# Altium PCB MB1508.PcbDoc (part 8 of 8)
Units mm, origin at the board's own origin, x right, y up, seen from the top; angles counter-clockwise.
Board outline 129 x 77 mm, 4 copper layers (Top Layer, GND, POWER, Bottom Layer), stack 1.582 mm thick; 399 components, 297 nets, 1407 pads, 1316 vias.
Unrouted connection lines stored in the file: 535.
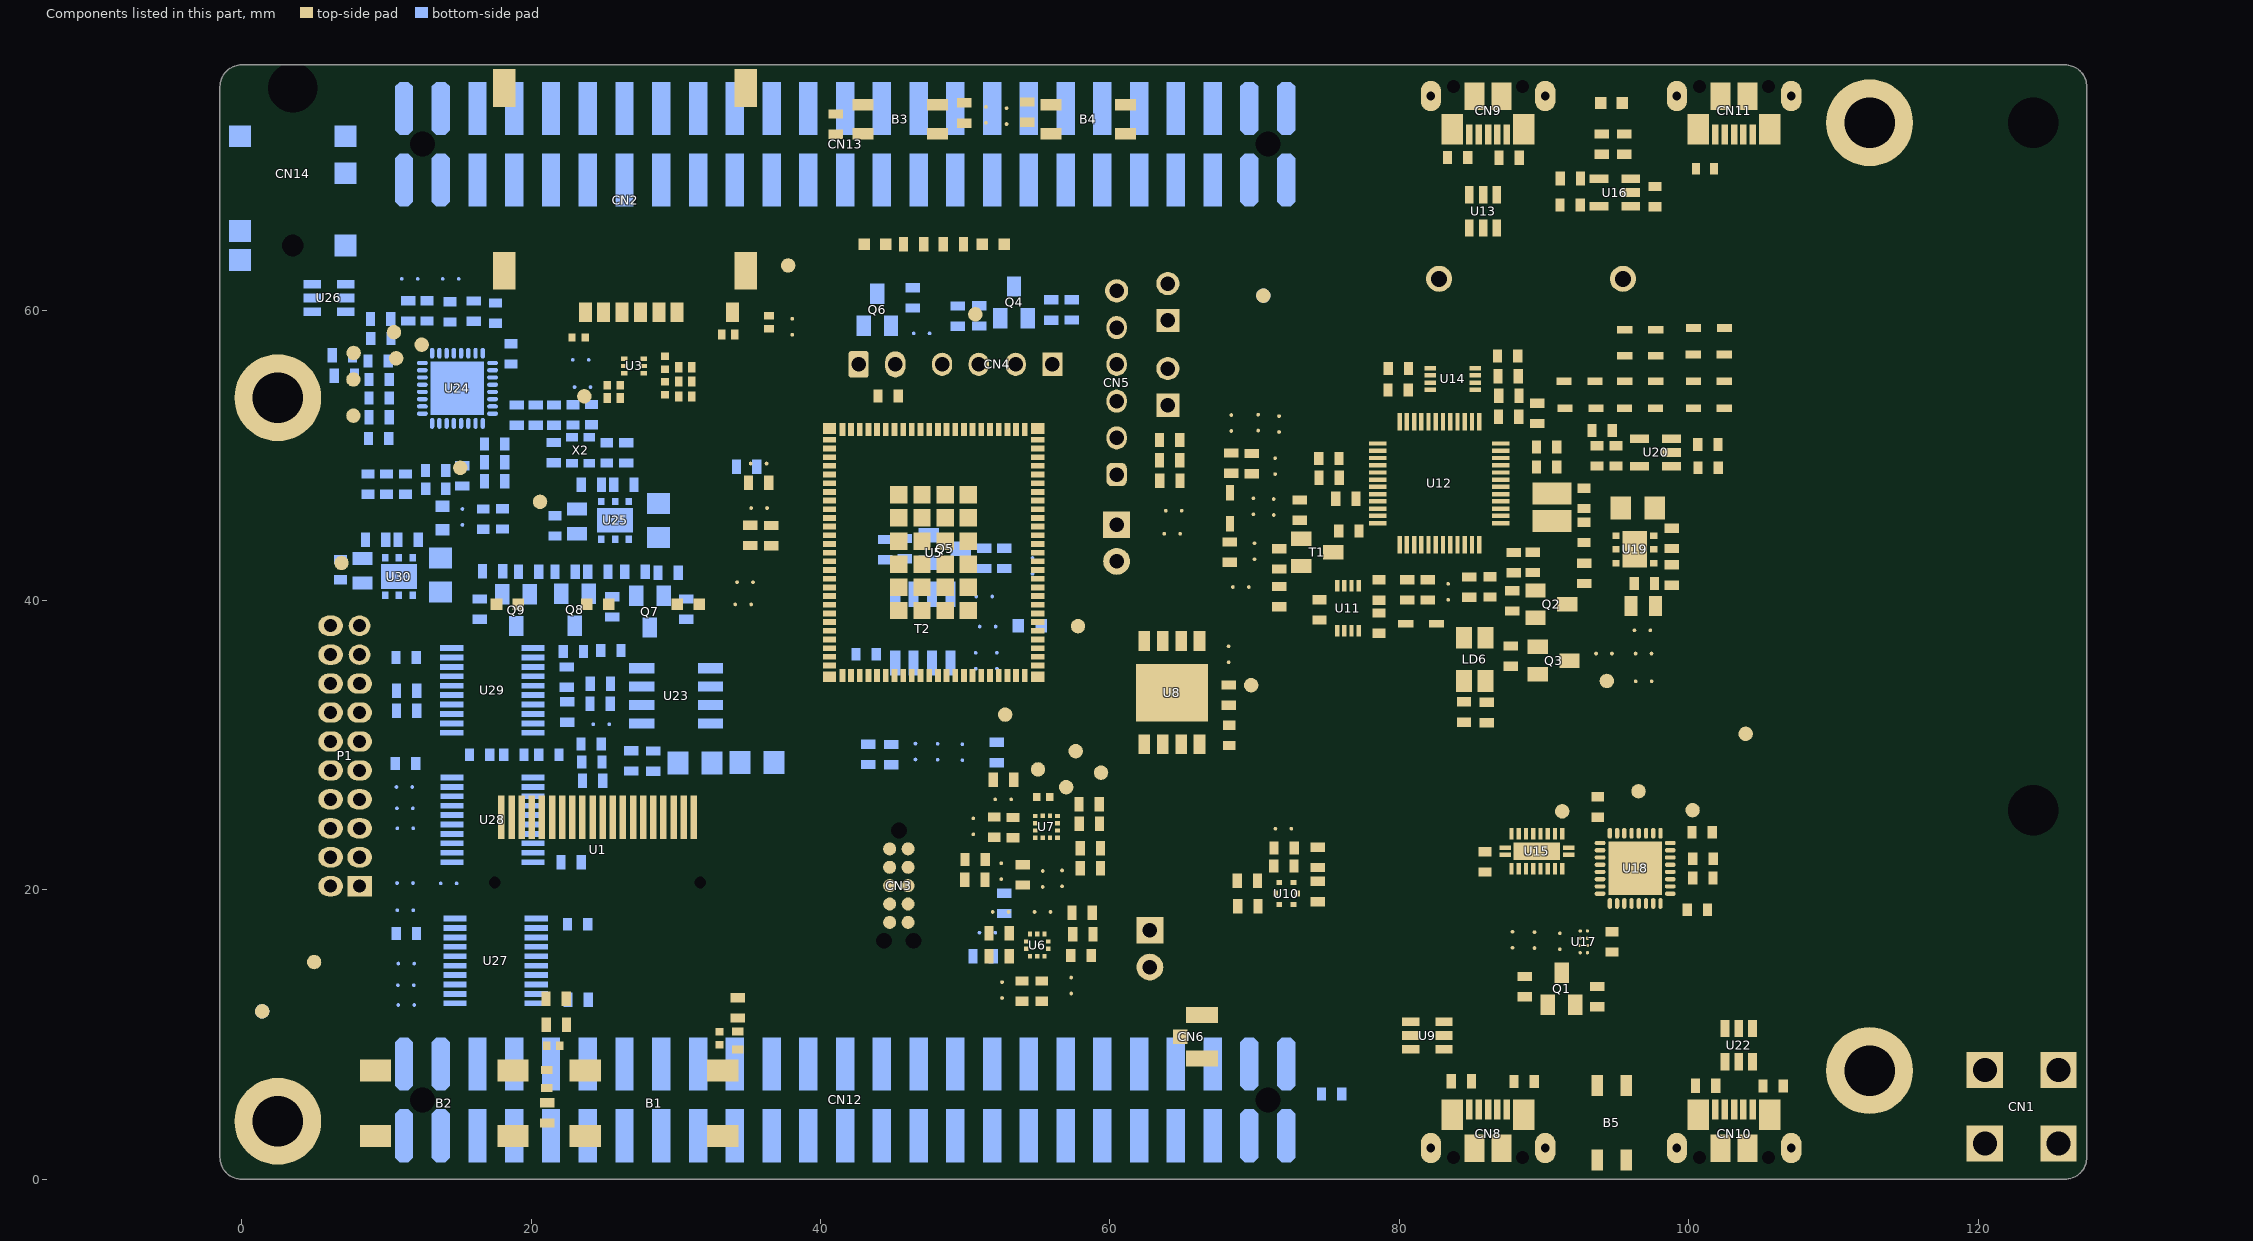
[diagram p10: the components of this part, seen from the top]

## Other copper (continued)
Bottom Layer:
  rectangle net 3V3: 21.08,45.83 23.352,46.772
  rectangle net 3V3: 24.95,37.795 26.145,38.78
  rectangle net 1V8: 25.866,35.418 27.034,36.242
  rectangle net GND: 27.675,43.641 30.07,45.734
  rectangle net GND: 23.59,16.793 24.556,18.111
  rectangle net GND: 22.77,20.927 24.204,22.403
  rectangle net GND: 45.498,43.506 48.489,44.882
  rectangle net GND: 52.228,41.367 53.296,42.509
  rectangle net GND: 52.075,58.551 53.483,60.041
  rectangle net GND: 54.985,60.516 56.469,61.426
  rectangle net GND: 27.96,29.02 29.112,29.923
  rectangle net GND: 31.313,27.459 32.618,29.897
  rectangle net GND: 42.5,58.337 43.844,59.956
  rectangle net GND: 9.94,27.943 11.291,29.567
  rectangle net GND: 10.099,35.382 11.375,36.741
  rectangle net GND: 28.26,39.289 29.402,40.88
  region net GND: 41.285,10.315 40.618,10.143 40.435,9.96 40.532,9.864 40.532,9.745 40.636,9.868 41.211,10.095
  region net GND: 41.211,10.095
  pour cut-out: 11.823,67.466 13.444,67.466 13.486,67.509 13.486,71.973 13.022,72.437 11.406,72.437 11.406,72.33 11.207,72.131
  pour cut-out: 10.31,71.79 10.273,71.752 10.273,70.568 10.683,70.568 11.036,70.92 11.313,70.92 11.313,71.349 11.83,71.866 11.563,72.133 11.563,72.243
  region net 5V: 10.218,73.177 10.218,72.261 10.557,71.922 11.184,72.55 11.189,72.55 11.189,73.083 11.101,73.171
  region net 1V8_MD: 42.765,42.308 43.409,42.308 43.573,42.472 43.573,43.359 43.425,43.507 43.407,43.507
  region net GND: 63.471,62.946 62.947,62.421 63.019,62.349 63.054,62.349 63.62,62.915 63.729,62.915
  region net GND: 52.851,39.573 52.563,39.259 52.547,39.048 52.671,38.903 52.7,38.895 52.918,38.858 53.223,39.162 53.223,39.234
  region net GND: 52.875,39.763
  region net GND: 22.77,22.403 23.124,22.757 23.528,22.757 23.616,22.845 23.733,22.728 23.733,21.909 23.743,21.899
  pour cut-out: 23.489,48.941 24.707,48.941 24.708,48.943 24.779,48.871 24.779,47.663 24.64,47.663 24.356,47.379 24.148,47.588 23.311,47.588
  region net GND: 51.785,41.533 52.215,41.93 52.215,41.962 52.248,41.962 52.369,42.083 52.496,41.956 52.496,41.483 52.555,41.424 52.496,41.364 52.496,41.311 51.812,41.311 51.726,41.225
  pour cut-out: 52.875,39.763 52.851,39.646 52.785,38.992 52.651,38.992 52.51,38.851 52.423,38.938 52.254,38.938 52.207,38.992
  pour cut-out: 15.613,30.094 19.116,30.094 19.13,30.108 19.247,29.992 19.247,29.142 19.09,28.985 17.134,28.985 17.096,28.947 17.027,29.016 15.677,29.016 15.677,29.02 15.66,29.037
  pour cut-out: 53.766,39.026 55.257,39.026 55.257,38.251 55.089,38.082 55.089,37.257 54.459,37.257 54.443,37.273
  pour cut-out: 19.439,42.769 19.448,42.778 20.627,42.778 20.627,41.775 20.275,41.422 20.275,40.864 18.814,40.864 18.484,41.194
  pour cut-out: 24.252,36.169 25.707,36.169 25.728,36.19 25.812,36.106 25.812,35.936 25.787,35.936 25.558,35.708 25.524,35.741 25.399,35.741
  pour cut-out: 25.587,37.541 25.587,37.111 25.669,37.029 26.257,37.029 26.257,37.265 26.461,37.468 26.308,37.62 26.308,37.638
  pour cut-out: 28.829,35.956 28.829,36.424 28.926,36.521 27.485,36.521 27.248,36.283 27.248,36.042 27.259,36.042 27.641,35.66 27.788,35.66
  pour cut-out: 11.298,21.293 12.316,21.293 12.339,21.269 12.276,21.206 12.276,21.086 12.181,21.086 12.174,21.078 12.123,21.129 11.237,21.129 11.234,21.132
  region net 3V6: 6.802,43.089 7.034,43.322 7.034,44.199 8.018,44.199 8.047,44.199 8.084,44.199 8.565,44.199 8.565,43.144 8.766,42.943
  region net 3V6: 9.258,43.066 9.385,43.193 8.753,43.826 8.135,43.826 7.656,43.347 7.576,43.347 7.784,43.139 7.784,43.016
  region net 3V6: 9.534,42.86 9.131,42.457 7.197,42.457 6.264,42.457 6.252,42.517 6.252,43.534 7.034,44.199
  region net 5V: 12.974,43.641 12.007,43.193 12.007,43.135 11.816,42.943 11.897,42.863 13.591,42.863 13.511,42.943
  region net 5V: 12.376,42.761 12.403,42.761 12.949,42.215 13.274,42.54 13.432,42.54 13.432,42.786 13.127,43.091 13.127,43.117 12.263,43.117
  region: 41.47,43.751
  region net 1V8: 40.841,44.263 41.315,43.789 41.614,43.789 41.917,44.092 41.917,45.386 41.728,45.576 41.208,45.576 41.208,44.629
  region net 1V8: 41.208,45.576 40.621,44.988 40.623,44.264 41.252,44.862 41.299,44.862 41.324,44.888
  pour cut-out: 24.987,56.287 25.011,56.264 25.011,55.236 24.564,55.236 24.374,55.046 24.226,55.194 24.186,55.194 24.186,55.376 24.081,55.481
  region net GND: 15.971,18.264 15.613,18.621 15.423,18.621 15.881,18.163
  region net GND: 8.401,42.097 10.012,42.097 10.122,41.986 9.916,41.781 9.916,41.055 9.64,40.806 8.262,40.797
  region net GND: 13.742,40.578 14.854,41.691 14.961,41.691 14.961,40.914 15.522,40.352 15.053,39.883 15.053,39.61 14.697,39.253
  region net GND: 12.487,42.244 12.247,42.485 12.091,42.485 12.091,42.25 11.903,42.062 11.903,41.022 12.125,40.799 12.562,40.799 12.565,40.797 12.565,40.804
  region net GND: 6.888,42.032 6.888,40.776 6.869,40.756 7.928,40.756 7.928,41.002 8.436,41.511 8.381,41.566 8.381,42.008
  region net GND: 12.628,41.7 13.58,41.7 13.717,41.563 13.717,40.399 13.05,39.732 12.587,39.732 12.587,39.769 12.579,39.776
  region net GND: 12.367,61.291 12.374,61.284 12.374,60.052 12.36,60.038 14.404,60.038 14.45,60.084 14.45,61.273 14.39,61.333
  region net GND: 11.971,61.457 10.088,61.457 10.099,61.445 10.099,61.275 10.127,61.248 12.519,61.253 12.56,61.294
  pour cut-out: 12.355,60.553 12.4,60.509 12.4,59.617 12.112,59.617 12.023,59.528 11.758,59.794 10.859,59.794 10.859,59.927 10.579,60.207
  pour cut-out: 13.1,45.989 13.1,44.603 13.201,44.502 13.403,44.704 14.229,44.704 14.229,45.153 14.679,45.604 14.541,45.741 14.541,46.09 13.962,46.09 13.853,46.2 13.825,46.172 13.752,46.172
  pour cut-out: 9.135,45.246 9.144,45.246 9.576,44.814 9.576,43.685 9.512,43.621 9.301,43.832 9.108,43.832 9.108,43.841 9.089,43.86
  pour cut-out: 19.806,52.781 19.806,53.109 18.789,53.109 18.725,53.061 18.725,52.717 18.773,52.717 19.189,52.3 19.789,52.308
  region net GND: 27.44,46.053 27.054,46.368 27.023,46.368 27.023,46.337 26.759,46.073 26.86,45.972 26.86,44.793 26.969,44.793 27.399,44.363
  region net GND: 24.167,46.035 24.499,46.367 24.915,46.367 25.221,46.06 25.146,45.985 25.146,45.273 24.16,44.287 24.16,43.762 24.06,43.663 23.225,43.668 23.125,43.768 24.015,44.657 24.015,45.369
  region net GND: 23.287,43.738 23.287,43.761 23.638,44.113 23.573,44.178 23.573,44.438 23.293,44.438 23.166,44.311 23.115,44.311
  region net GND: 16.287,45.725 16.287,46.14 16.342,46.196 16.389,46.149 18.504,46.149 19.002,45.65
  pour cut-out: 15.66,39.597 15.66,39.144 17.111,39.133 17.111,39.567 16.978,39.567 16.837,39.708 16.759,39.63 15.95,39.63
  pour cut-out: 9.889,19.878 9.866,19.855 9.866,19.173 12.811,19.173 13.132,19.494 13.132,20.266 11.232,20.266 10.997,20.031 10.78,20.031
  region net GND: 15.971,18.328 15.677,18.621 15.613,18.621 15.613,18.533 15.611,18.531 15.712,18.43 15.712,18.413 15.736,18.413 15.945,18.205 15.948,18.205
  pour cut-out: 50.188,5.812 51.235,5.812 51.156,5.891 51.156,7.575 50.539,8.192 49.971,8.192
  pour cut-out: 42.163,4.82 43.601,4.82 43.678,4.742 44.155,5.219 44.155,6.489 43.987,6.657 43.987,9.351 43.781,9.351 43.027,10.105 42.982,10.06 42.408,10.06 42.408,9.886 41.931,9.409 42.092,9.248 42.092,6.147 41.409,6.147 41.197,5.935 41.641,5.49 41.641,4.968
  pour cut-out: 55.179,10.093 56.249,10.093 56.249,8.74 56.267,8.722 56.185,8.64 56.185,7.287 55.792,7.287 55.143,6.638 55.042,6.739 54.275,6.739
  pour cut-out: 57.793,5.875 57.798,5.87 58.712,5.87 58.712,6.267 58.716,6.272 58.575,6.414 58.575,6.784 58.383,6.784 58.036,7.131 57.999,7.095 57.793,7.095 57.793,7.058 57.652,6.917
  pour cut-out: 60.092,6.245 60.626,5.711 60.626,4.975 60.672,4.929 60.663,4.92 59.37,4.92 59.2,5.089 59.2,5.695
  pour cut-out: 51.86,3.005 57.5,3.005 56.809,3.697 56.809,5.463 55.614,5.463 55.025,6.052 54.682,5.709 53.799,5.709
  pour cut-out: 69.821,2.757 71.858,2.757 72.013,2.912 72.013,5.047 71.662,5.398 71.58,5.316 70.386,5.316 70.386,4.757 70.315,4.687
  pour cut-out: 53.509,18.984 53.859,19.131 53.913,19.131 53.913,19.547 53.806,19.654 53.436,19.654 53.379,19.711 53.317,19.649 52.877,19.649 52.51,19.282 52.219,19.282 52.219,18.853 52.446,18.626 52.664,18.626 52.679,18.611
  pour cut-out: 44.164,10.074 44.185,10.095 52.389,10.095 52.389,8.1 51.865,7.576 51.659,7.781 47.711,7.781 46.21,6.28 46.21,0.955 45.038,0.955 44.534,1.458 44.308,1.458 44.308,1.623 44.524,1.838
  region net GND: -1.041,51.114 -1.041,54.306 -0.936,54.41 -0.881,54.355 -0.881,50.571 -0.849,50.539
  pour cut-out: 14.264,72.11 15.779,72.11 15.779,70.297 15.576,70.094 15.755,69.915 15.755,66.873 14.455,66.873 14.216,67.111 14.216,67.696
  pour cut-out: 17.108,70.924 17.481,70.924 18.366,70.038 18.366,67.458 18.32,67.458 17.9,67.038 17.831,67.108 16.695,67.108 16.695,67.199 16.675,67.219
  pour cut-out: 27.285,70.889 27.344,70.831 31.247,70.831 31.247,69.572 31.328,69.491 31.072,69.235 31.072,66.31 27.961,66.31 27.763,66.112 26.808,67.067 26.155,67.067
  pour cut-out: 31.748,71.164 46.417,71.164 46.417,68.162 46.696,67.882 46.114,67.3 34.299,67.3 33.647,66.648 33.437,66.857 32.179,66.857 32.179,68.349 31.748,68.78
  region net GND: 43.957,71.321 43.975,71.339 44.656,71.339 44.656,71.26 44.679,71.237 44.627,71.185 43.81,71.185 43.667,71.328 43.666,71.328
  region net GND: 45.845,71.164 47.549,71.164 47.571,71.185 47.546,71.209 47.546,71.386 47.387,71.386 47.329,71.328 47.317,71.34 46.325,71.34
  pour cut-out: 17.004,76.138 18.154,76.138 18.154,72.364 18.498,72.02 18.498,70.88 18.532,70.846 18.352,70.665 17.254,70.665 16.885,71.034 16.74,71.034 16.74,71.311 16.732,71.318
  pour cut-out: 60.022,70.982 60.05,71.01 61.254,71.01 61.254,70.906 61.394,70.765 61.238,70.609 61.238,66.746 59.745,66.746 59.521,66.97 59.497,66.947 59.441,66.947
  pour cut-out: 57.74,69.113 59.071,69.113 58.815,68.856 58.815,67.516 58.871,67.46 58.462,67.051 57.667,67.051 57.659,67.043 57.627,67.075 57.387,67.075
  region net GND: 65.211,71.738 65.638,72.165 65.638,71.859 65.459,71.68 65.326,71.68 65.316,71.67
  pour cut-out: 26.114,29.383 26.128,29.369 26.128,28.514 27.93,28.514 27.982,28.566 27.982,30.571 27.392,31.161 26.093,31.161
  pour cut-out: 22.054,45.178 24.032,45.185 24.032,45.621 24.062,45.65 23.93,45.782 23.93,45.973 22.735,45.973
  region net GND: 30.199,46.513 30.199,48.57 30.048,48.721 30.043,46.575 30.071,46.546 30.071,46.17
  region net GND: 52.438,58.367 52.226,58.367 51.923,58.67 51.923,58.801 52.028,58.801 52.151,58.923 52.883,58.923 53.187,58.619 53.492,58.619 53.492,58.475 53.453,58.436
  pour cut-out: 42.512,30.146 42.492,30.126 42.492,28.02 43.901,28.02 44.853,28.972 45.988,28.972 45.988,29.05 44.938,30.1 44.292,30.1
  pour cut-out: 52.952,28.657 52.946,29.4 52.969,30.374 52.971,30.44 52.971,30.497 52.631,30.497 52.565,30.563 52.185,30.184 52.165,30.184 52.165,30.028 51.945,29.808 51.945,29.559 51.905,29.519 51.905,29.486
  pour cut-out: 16.873,50.367 16.915,50.409 17.734,50.409 17.734,50.04 17.796,49.978 17.734,49.916 17.734,47.431 16.881,47.431 16.829,47.379 16.647,47.561 16.466,47.561
  pour cut-out: 23.325,53.273 23.325,51.585 23.4,51.51 23.462,51.572 24.896,51.572 24.896,53.8 24.915,53.819 24.867,53.867 23.675,53.867 23.323,53.515
  pour cut-out: 12.04,5.75 25.863,5.75 26.093,5.98 26.093,10 25.636,10.456 25.293,10.113 11.664,10.113 11.343,9.964 11.307,9.928 11.307,6.861 11.825,6.343 11.68,6.197 11.68,5.904
  region net GND: 15.976,5.75 16.711,5.75 16.864,5.597 17,5.597 17,5.539 16.903,5.636 15.809,5.636
  pour cut-out: 19.413,1.826 19.426,1.838 20.866,1.838 20.866,2.927 21.249,3.31 20.287,4.272 20.287,4.998 19.191,4.998 19.159,4.967
  pour cut-out: 18.154,76.135 18.168,76.121 21.277,76.121 21.293,76.138 23.4,76.138 23.4,72.243 20.904,69.747 20.904,67.232 20.834,67.232 20.451,66.85 20.267,67.034 18.651,67.034 18.651,67.404
  region net GND: 26.017,71.442 26.358,71.382 26.976,71.382 26.976,71.313 26.991,71.298 26.879,71.185 25.88,71.185 25.718,71.347 25.718,71.545
  region net GND: 28.065,71.185 29.935,71.185 29.935,71.45 29.867,71.382 28.327,71.382
  pour cut-out: 24.855,76.135 24.869,76.121 25.84,76.121 25.84,74.724 26.017,74.547 26.017,72.85 24.92,72.85 24.42,72.35 23.92,72.85 23.53,72.85
  region net GND: 17.234,19.145 17.238,19.14 17.935,19.14 18.066,19.272 17.242,19.272 17.212,19.242 17.017,19.242
  region net GND: 16.663,52.225 16.747,52.141 16.747,50.997 16.836,50.997 17.33,51.491 17.33,51.868 17.116,52.083
  region net GND: 22.617,29.599 22.578,29.599 22.178,29.199 22.026,29.351 21.788,29.351 21.788,29.985 22.027,30.224 22.573,30.224 22.574,30.225
  region net UartUsbVbus: 104.951,18.52 104.488,18.846 104.29,18.999 103.988,19.483 103.988,19.929 104.178,20.082 104.392,20.097 104.716,19.89 105.112,19.89 105.348,19.653 105.348,18.648 105.22,18.52
  region net 3V3_STLK: 92.968,50.238 93.114,50.092 93.114,49.074 92.996,48.956 91.899,48.956 91.794,49.061 91.794,50.121 91.911,50.238
  region net 5V: 91.953,54.835 92.099,54.689 92.099,53.672 91.98,53.553 90.884,53.553 90.779,53.658 90.779,54.718 90.895,54.835
  region net EXT_BAT: 95.176,56.093 95.311,55.958 95.311,55.681 94.785,55.155 94.785,55.002 94.632,54.849 94.369,54.849 94.197,55.02 94.197,55.438 94.101,55.535 93.503,55.535 93.375,55.663 93.375,55.968 93.5,56.093
  region net VBUS: 94.058,54.134 95.182,54.134 95.328,53.988 95.328,53.704 95.155,53.53 94.936,53.53 94.896,53.49 94.896,53.026 94.753,52.882 94.438,52.882 94.326,52.995 94.326,53.514 94.244,53.597 94.045,53.597 93.931,53.711 93.931,54.007 94.058,54.134
  region net GND: 93.953,54.591 94.848,54.591 94.91,54.528 94.91,54.493 94.819,54.493 94.765,54.44 93.933,54.44
  region net GND: 115.5,5.575
  region net GND: 115.5,9.087 115.5,3.971 115.319,3.971 114.419,4.871 114.546,4.999 114.546,11.105
  region net GND: 115.5,74.575 115.5,69.459 115.319,69.459 114.419,70.359 114.546,70.487 114.546,76.492
  region net GND: 5.55,55.14 5.702,54.603 5.883,54.603 5.802,54.685 5.677,55.165 5.594,55.248 5.594,55.279
  region net GND: 4.494,56.937 4.494,51.794 4.885,51.402 5.147,51.664 5.785,51.664 5.785,52.412 5.883,52.51 5.883,54.603 5.721,54.79 5.594,55.601 5.287,55.908 5.287,56.902
  pour cut-out: 6.744,54.091 6.801,54.034 7.299,54.034 7.299,55.034 7.696,55.43 7.542,55.584 7.542,56.355 7.423,56.355 6.978,56.8 6.748,56.57 6.666,56.57
  text "4" at 110.674,39.22 h0.89 r270
Multi-Layer:
  pour cut-out: 119.194,8.531 115.5,8.531 115.5,77 127.5,77 127.5,8.506
  pour cut-out: 53.93,17.227 56.03,17.227 56.03,15.127 53.93,15.127
  pour cut-out: 54.559,25.396 56.659,25.396 56.659,23.296 54.559,23.296
  pour cut-out: 71.146,20.787 73.246,20.787 73.246,18.687 71.146,18.687
  pour cut-out: 110,37.757 112.131,37.757 112.131,43.685 110,43.685

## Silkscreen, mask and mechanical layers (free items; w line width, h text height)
Top Overlay:
  circle w0.254: c85.895,38.735 r0.254
  rectangle: 107.5,13 116.5,38
  rectangle: 107.5,43.3 116.5,68.3
  rectangle: 46.96,53.466 49.297,54.666
  region: 57.468,54.666 55.131,54.666 55.131,53.466 57.468,53.466
  lines w0.127: 10.746,41.052 10.77,41.076 ; 36.038,18.591 41.702,18.591 ; 38.206,26.657 47.198,26.657 49.23,24.625 49.23,22.062 ; 41.406,30.111 48.128,30.111 49.195,29.044 49.195,28.472 49.195,25.911 ; 48.833,26.273 49.195,25.911 ; 48.867,22.424 49.23,22.062 ; 49.195,25.934 49.195,25.911 ; 49.557,26.273 49.195,25.911 ; 49.592,22.424 49.23,22.062 ; 49.976,27.209 50.338,26.846 ; 50.338,30.529 50.338,26.846 ; 50.7,27.209 50.338,26.846 ; 57.371,59.639 57.751,59.259 57.751,57.556 ; 60.825,68.802 61.231,68.802 ; 60.825,76.448 61.231,76.448 ; 62.044,68.802 62.451,68.802 ; 62.044,76.448 62.451,76.448 ; 63.112,41.765 67.175,41.765 67.697,42.287 ; 72.076,47.425 72.403,47.751 73.753,47.751 ; 72.289,50.498 73.221,51.43 76.977,51.43 ; 72.383,53.727 73.35,54.694 76.879,54.694 ; 76.38,48.397 77.371,48.397 77.54,48.566 77.54,49.967 ; 91.724,48.743 95.376,48.743 95.662,48.457 104.641,48.457 ; 98.2,36.145 98.519,35.826 98.519,35.299 ; 98.27,37.509 98.653,37.127 98.653,36.874 ; 98.347,40.176 105.89,40.176 ; 46.96,53.466 46.96,54.666 49.246,54.666 49.246,53.466 46.96,53.466 ; 46.96,57.951 49.246,57.951 49.246,59.151 46.96,59.151 46.96,57.951 ; 55.182,57.951 55.182,59.151 57.468,59.151 57.468,57.951 55.182,57.951
  lines w0.2: 39.819,69.513 39.819,68.802 40.251,68.802 ; 39.819,70.072 39.819,70.555 ; 39.819,70.936 39.819,71.418 ; 39.819,71.799 39.819,72.282 ; 39.819,72.739 39.819,73.222 ; 39.819,73.527 39.819,74.009 ; 39.819,74.314 39.819,74.797 ; 39.819,75.127 39.819,75.609 ; 39.819,75.965 39.819,76.448 40.251,76.448 ; 40.657,68.802 41.14,68.802 ; 40.657,76.448 41.14,76.448 ; 41.597,68.797 42.08,68.797 ; 41.597,76.442 42.08,76.442 ; 42.56,68.802 43.042,68.802 ; 42.56,76.448 43.042,76.448 ; 43.502,68.802 43.985,68.802 ; 43.502,76.448 43.985,76.448 ; 44.366,68.802 44.848,68.802 ; 44.366,76.448 44.848,76.448 ; 45.229,68.802 45.712,68.802 ; 45.229,76.448 45.712,76.448 ; 46.093,68.802 46.576,68.802 ; 46.093,76.448 46.576,76.448 ; 46.931,68.802 47.414,68.802 ; 46.931,76.448 47.414,76.448 ; 47.719,68.802 48.201,68.802 ; 47.719,76.448 48.201,76.448 ; 48.531,68.802 49.014,68.802 ; 48.531,76.448 49.014,76.448 ; 49.42,68.802 49.903,68.802 ; 49.42,76.448 49.903,76.448 ; 50.335,68.802 50.817,68.802 ; 50.335,76.448 50.817,76.448 ; 51.224,68.802 51.706,68.802 ; 51.224,76.448 51.706,76.448 ; 52.138,68.802 52.621,68.802 ; 52.138,76.448 52.621,76.448 ; 53.027,68.802 53.51,68.802 ; 53.027,76.448 53.51,76.448 ; 53.891,68.802 54.373,68.802 ; 53.891,76.448 54.373,76.448 ; 54.704,68.802 55.186,68.802 ; 54.704,76.448 55.186,76.448 ; 55.628,68.802 56.11,68.802 ; 55.628,76.448 56.11,76.448 ; 56.532,68.802 57.015,68.802 ; 56.532,76.448 57.015,76.448 ; 57.371,68.802 57.853,68.802 ; 57.371,76.448 57.853,76.448 ; 58.209,68.802 58.691,68.802 ; 58.209,76.448 58.691,76.448 ; 59.047,68.802 59.53,68.802 ; 59.047,76.448 59.53,76.448 ; 59.86,68.802 60.342,68.802 ; 59.86,76.448 60.342,76.448 ; 60.749,68.802 61.231,68.802 ; 60.749,76.448 61.231,76.448 ; 61.079,68.802 61.562,68.802 ; 61.079,76.448 61.562,76.448 ; 61.968,68.802 62.451,68.802 62.451,69.513 ; 61.968,76.448 62.451,76.448 62.451,75.965 ; 62.451,70.072 62.451,70.555 ; 62.451,70.936 62.451,71.418 ; 62.451,71.799 62.451,72.282 ; 62.451,72.739 62.451,73.222 ; 62.451,73.527 62.451,74.009 ; 62.451,74.314 62.451,74.797 ; 62.451,75.127 62.451,75.609 ; 127.5,20.5 119.8,20.5 119.8,76.5 127.5,76.5
  text "ST-LINK/V2-1" at 78.199,75.88 h1.3 r270
  text "MDM" at 40.454,69.945 h1.3
  text "Shut down" at 43.528,69.92 h1.3
  text "MDM RST" at 55.543,69.869 h1.3
  text "USB PWR" at 102.36,68.534 h1.3
  text "uSIM" at 14.264,68.359 h1.3
  text "E" at 3.571,67.197 h15
  text "K" at 65.805,66.378 h17
  text "SWD" at 59.677,63.125 h1.3
  text "TX_IND" at 50.375,62.941 h1.3
  text "PSM_IND" at 40.302,62.824 h1.3
  text "GND" at 36.531,61.342 h1.3
  text "VDD_MD" at 45.153,61.078 h1.3
  text "GND" at 6.497,60.494 h1.3 r270
  text "Idd" at 41.248,58.217 h1.3
  text "ST-LINK" at 49.881,58.114 h1.3
  text "TX" at 65.753,57.404 h1.52 r270
  text "RX" at 65.613,54.97 h1.52 r270
  text "DISCOVERY" at 49.394,54.014 h1.1
  text "VDD_SIM" at 18.668,51.88 h1.3
  text "3V3" at 17.823,45.212 h1.3
  text "3V6" at 7.917,42.261 h1.3
  text "STMod+" at 2.758,40.204 h1.3
  text "NRST" at 57.024,40.165 h1.3
  text "1V8" at 92.606,38.93 h1.3
  text "AVDD" at 58.704,38.004 h1.3
  text "COM" at 80.208,33.916 h1.3
  text "1V8_MD" at 93.222,31.416 h1.3
  text "GND" at 102.715,29.111 h1.3
  text "H" at 72.739,27.782 h15
  text "1V8" at 101.142,24.93 h1.52
  text "HUM_INT" at 60.668,19.282 h1.3
  text "I" at 9.091,13.494 h10
  text "F" at 31.031,13.43 h10
  text "C" at 13.948,13.292 h10
  text "G" at 22.732,13.229 h10
  text "GND" at 3.809,12.998 h1.3
  text "TAG-10" at 43.854,12.625 h1.3
  text "PRE_INT" at 61.083,12.359 h1.3
  text "SMA" at 124.182,9.652 h1.3
  text "USB-UART" at 108.201,7.763 h1.3 r270
  text "User USB" at 79.707,7.117 h1.3 r270
  text "Recovery" at 91.759,5.858 h1.3 r270
  text "MB1508C" at 36.722,4.224 h3
  text "USER / Tamper" at 10.705,1.133 h1.3
  text "J" at 51.904,1.14 h17
  text "Reset" at 26.933,0.712 h1.3
Bottom Overlay:
  lines w0.127: -0.859,29.368 15.016,29.368 ; 1.061,48.779 7.627,48.779 7.886,49.038 8.286,49.438 12.055,49.438 ; 1.212,42.99 6.138,42.99 ; 1.261,46.094 13.174,46.089 ; 2.758,58.334 3.596,58.334 5.877,56.053 ; 2.86,59.178 4.238,59.178 5.911,57.505 ; 5.594,52.056 8.262,54.761 ; 5.975,57.931 7.844,57.931 8.521,57.254 ; 6.397,52.056 8.258,54.007 ; 7.947,52.47 8.336,52.945 ; 10.554,50.641 10.991,50.204 12.597,50.204 ; 12.614,19.888 12.982,19.521 24.482,19.521 ; 14.66,29.012 15.016,29.368 ; 14.66,29.723 15.016,29.368 ; 18.18,61.185 18.527,61.532 26.842,61.532 ; 23.258,75.921 23.258,76.479 ; 24.431,70.608 24.431,70.621 24.834,71.024 27.308,71.024 ; 27.538,36.429 27.563,36.404 33.151,36.404 ; 30.443,43.589 36.006,43.589 ; 32.457,36.404 32.669,36.404 ; 57.065,66.511 57.065,67.019 ; 67.225,66.511 67.225,67.019 ; 72.978,75.336 73.74,75.336
  text "RX" at 39.778,76.057 h1.1
  text "TX" at 42.368,76.057 h1.1
  text "1V8_MD" at 27.018,76.048 h1
  text "DWU" at 35.105,76.037 h1.1
  text "GND" at 37.74,76.037 h1.1
  text "CTS" at 45.174,76.037 h1.1
  text "RTS" at 47.537,76.037 h1.1
  text "RSTR" at 60.464,76.033 h1.1
  text "TXI" at 65.326,76.033 h1.1
  text "3V3" at 22.23,76.023 h1.1
  text "RSTI" at 50.358,76.008 h1.1
  text "GND" at 63.104,76.008 h1.1
  text "PSMI" at 68.124,76.008 h1.1
  text "HWU" at 32.551,75.997 h1.1
  text "5V" at 11.752,75.971 h1.1
  text "VDDIO_MOM" at 79.24,75.159 h1
  text "Audio" at 9.822,75.006 h1.3
  text "SCLK" at 65.524,65.808 h1.1
  text "SIO" at 60.19,65.765 h1.1
  text "SRST" at 62.977,65.765 h1.1
  text "VDD_SIM" at 57.875,65.7 h1.1
  text "GND" at 25.1,65.578 h1.1
  text "GND" at 50.44,65.56 h1.1
  text "VDD_MD" at 70.95,65.56 h1.3
  text "3V3" at 22.8,46.986 h1.3
  text "PB5" at 57.602,10.973 h1.1
  text "PB10" at 45.363,10.556 h1
  text "PC12" at 19.855,10.509 h1
  text "PB11" at 42.695,10.456 h1
  text "PB14" at 40.022,10.414 h1
  text "PB8" at 50.222,10.401 h1.1
  text "PB1" at 70.426,10.414 h1.1
  text "PB0" at 72.865,10.414 h1.1
  text "PB15" at 34.899,10.389 h1
  text "GND" at 37.341,10.389 h1
  text "PB9" at 47.617,10.373 h1.1
  text "PB7" at 52.636,10.373 h1.1
  text "PB4" at 60.825,10.375 h1.1
  text "GND" at 63.29,10.389 h1.1
  text "PB3" at 65.422,10.389 h1.1
  text "PB2" at 67.912,10.373 h1.1
  text "PC6" at 32.206,10.35 h1.1
  text "PC7" at 29.762,10.296 h1
  text "PB6" at 55.234,10.315 h1.1
  text "PC13" at 17.148,10.287 h1
  text "PC11" at 22.42,10.281 h1
  text "PC10" at 25.049,10.287 h1
  text "PC9" at 27.416,10.281 h1
  text "1V8" at 14.163,10.218 h1.1
  text "PH3" at 11.844,10.207 h1.1
  text "PA15" at 29.888,0.406 h0.9
  text "PA14" at 32.529,0.406 h0.9
  text "PA11" at 39.87,0.406 h0.9
  text "PC3" at 17.174,0.381 h1.1
  text "PA13" at 35.044,0.381 h0.9
  text "PA12" at 37.584,0.381 h0.9
  text "PH1" at 11.923,0.356 h1.1
  text "PC0" at 27.348,0.356 h1.1
  text "PA10" at 42.512,0.356 h0.9
  text "PA6" at 55.162,0.356 h1.1
  text "PA4" at 60.266,0.356 h1.1
  text "PA3" at 62.832,0.356 h1.1
  text "PA2" at 65.346,0.356 h1.1
  text "PA0" at 70.426,0.356 h1.1
  text "PH0" at 14.502,0.33 h1.1
  text "PC2" at 19.677,0.33 h1.1
  text "PC1" at 22.115,0.33 h1.1
  text "GND" at 24.871,0.33 h1.1
  text "PA5" at 57.726,0.33 h1.1
  text "PA1" at 67.886,0.33 h1.1
  text "AVDD" at 73.55,0.33 h1.1
  text "PA9" at 44.994,0.305 h1.1
  text "PA8" at 47.602,0.305 h1.1
  text "GND" at 50.335,0.305 h1.1
  text "PA7" at 52.646,0.305 h1.1
M1-Board Shape:
  lines w0.127: -1.5,3.499 -1.5,4.999
  lines w0.2: 0,77 ccw(c0,75.5) -1.5,75.5 -1.5,1.5 ccw(c0,1.5) 0,0 126,0 ccw(c126,1.5) 127.5,1.5 127.5,75.5 ccw(c126,75.5) 126,77 0.001,77
M2-Board Dimensions:
  lines w0.254: -18.5,3 -17.5,0 ; -18.5,74 -17.5,77 ; -17.754,0 -17.246,0 ; -17.754,77 -17.246,77 ; -17.5,33.36 -17.5,0 ; -17.5,43.64 -17.5,77 ; -16.5,3 -17.5,0 ; -16.5,74 -17.5,77 ; 0,0 -17.5,0 ; 0,77 -17.5,77
  text "77 (mm)" at -16.24,33.614 h3 r90
M3-Top Dimensions:
  lines w0.2: -6.969,20.251 6.15,20.246 ; -6.969,38.251 6.15,38.246 ; -3.941,19.096 -1.47,19.096 ; -3.941,39.396 -1.47,39.396
  lines w0.254: -13.5,7 -12.5,4 ; -13.5,51 -12.5,54 ; -12.754,4 -12.246,4 ; -12.754,54 -12.246,54 ; -12.5,23.852 -12.5,4 ; -12.5,34.148 -12.5,54 ; -11.5,7 -12.5,4 ; -11.5,51 -12.5,54 ; -7.969,23.251 -6.969,20.251 ; -7.969,35.251 -6.969,38.251 ; -7.223,20.251 -6.715,20.251 ; -7.223,38.251 -6.715,38.251 ; -6.969,24.193 -6.969,20.251 ; -6.969,34.309 -6.969,38.251 ; -5.969,23.251 -6.969,20.251 ; -5.969,35.251 -6.969,38.251 ; -4.94,22.096 -3.941,19.096 ; -4.94,36.396 -3.941,39.396 ; -4.195,19.096 -3.687,19.096 ; -4.195,39.396 -3.687,39.396 ; -3.941,23.282 -3.941,19.096 ; -3.941,35.209 -3.941,39.396 ; -2.941,22.096 -3.941,19.096 ; -2.941,36.396 -3.941,39.396 ; 2.5,4 -12.5,4 ; 2.5,54 -12.5,54 ; 112.5,7.5 129.866,7.5 ; 112.5,73 129.866,73 ; 123.508,10.483 124.175,8.483 ; 123.508,18.483 124.175,20.483 ; 123.921,8.483 124.429,8.483 ; 123.921,20.483 124.429,20.483 ; 124.175,11.025 124.175,8.483 ; 124.175,17.942 124.175,20.483 ; 124.842,10.483 124.175,8.483 ; 124.842,18.483 124.175,20.483 ; 128.866,10.5 129.866,7.5 ; 128.866,70 129.866,73 ; 129.612,7.5 130.12,7.5 ; 129.612,73 130.12,73 ; 129.866,33.976 129.866,7.5 ; 129.866,46.524 129.866,73 ; 130.866,10.5 129.866,7.5 ; 130.866,70 129.866,73
  text "65.5 (mm)" at 131.126,34.23 h3 r90
  text "18 (mm)" at -5.709,24.447 h3 r90
  text "50 (mm)" at -11.24,24.106 h3 r90
  text "20.3 (mm)" at -2.747,23.536 h3 r90
  text "12 (mm)" at 125.016,11.279 h2 r90
M7-Top Info:
  lines w0.2: -10.669,52.499 2.2,52.499
Drill Drawing:
  drawing of 424 lines, arcs and shapes, not listed
  text "4" at 170.448,131.87 h3
  text "5" at 272.661,131.87 h3
  text "TABLE" at 297.299,130.6 h3
  text "LAYER" at 176.27,130.346 h3
  text "STUCK-UP" at 188.333,130.346 h3
  text "IMPEDANCE" at 278.483,130.346 h3
  text "LAYER" at 273.169,124.123 h2
  text "IMPEDANCE" at 318.107,124.123 h2
  text "TOLERANCE" at 333.875,124.123 h2
  text "TRACE" at 283.169,124.059 h2
  text "SPACEING" at 293.169,124.059 h2
  text "Layer" at 170.67,124.044 h2
  text "Name" at 179.044,124.044 h2
  text "Material" at 195.24,124.044 h2
  text "Thickness" at 209.795,124.044 h2
  text "Constant" at 221.75,124.044 h2
  text "Board Layer Stack" at 232.814,124.044 h2
  text "IMPEDANCE" at 305.153,123.996 h2
  text "(MIL)" at 284.091,121.773 h2
  text "(MIL)" at 296.377,121.773 h2
  text "(SINGLE END)" at 304.665,121.71 h2
  text "(DIFFERENTIAL)" at 317.365,121.71 h2
  text "Top Overlay" at 179.044,120.044 h2
  text "Top Solder" at 179.044,116.044 h2
  text "Solder Resist" at 195.24,116.044 h2
  text "0.40mil" at 209.795,116.044 h2
  text "3.8" at 221.75,116.044 h2
  text "1" at 275.455,114.852 h2
  text "11" at 285.455,114.852 h2
  text "7" at 296.791,114.852 h2
  text "90 OHM" at 322.445,113.328 h2
  text "+/- 10%" at 337.431,113.328 h2
  text "N/A" at 309.491,112.82 h2
  text "4" at 275.201,112.312 h2
  text "11" at 285.615,112.312 h2
  text "7" at 296.791,112.312 h2
  text "1" at 170.67,112.044 h2
  text "Top Layer" at 179.044,112.044 h2
  text "Copper" at 195.24,112.044 h2
  text "1.20mil" at 209.795,112.044 h2
  text "Dielectric 1" at 179.044,108.044 h2
  text "FR-4" at 195.24,108.044 h2
  text "8.50mil" at 209.795,108.044 h2
  text "4.2" at 221.75,108.044 h2
  text "2" at 170.668,104.044 h2
  text "GND" at 179.044,104.044 h2
  text "Copper" at 195.24,104.044 h2
  text "1.20mil" at 209.795,104.044 h2
  text "Dielectric 2" at 179.044,100.044 h2
  text "40.50mil" at 209.795,100.044 h2
  text "4.4" at 221.75,100.044 h2
  text "3" at 170.67,96.044 h2
  text "POWER" at 179.044,96.044 h2
  text "Copper" at 195.24,96.044 h2
  text "1.20mil" at 209.795,96.044 h2
  text "Dielectric 3" at 179.044,92.044 h2
  text "8.50mil" at 209.795,92.044 h2
  text "4.2" at 221.75,92.044 h2
  text "4" at 170.67,88.044 h2
  text "Bottom Layer" at 179.044,88.044 h2
  text "Copper" at 195.24,88.044 h2
  text "1.20mil" at 209.795,88.044 h2
  text "Bottom Solder" at 179.044,84.044 h2
  text "Solder Resist" at 195.24,84.044 h2
  text "0.40mil" at 209.795,84.044 h2
  text "3.8" at 221.75,84.044 h2
  text "Bottom Overlay" at 179.044,80.044 h2
  text "Symbol" at 171.095,71.512 h2.4
  text "Count" at 179.686,71.512 h2.4
  text "Hole Size" at 189.603,71.512 h2.4
  text "Plated" at 207.719,71.512 h2.4
  text "Hole Type" at 215.245,71.512 h2.4
  text "Drill Layer Pair" at 226.285,71.512 h2.4
  text "Via/Pad" at 247.399,71.512 h2.4
  text "Pad Shape" at 256.359,71.512 h2.4
  text "Template" at 267.824,71.512 h2.4
  text "Description" at 294.368,71.512 h2.4
  text "Hole Tolerance (+)" at 306.272,71.512 h2.4
  text "Hole Tolerance (-)" at 325.127,71.512 h2.4
  text "Hole Length" at 343.258,71.512 h2.4
  text "Routed Path Length" at 360.457,71.512 h2.4
  text "1" at 179.686,67.508 h2
  text "1.500mm (59.06mil)" at 189.603,67.508 h2
  text "NPTH" at 207.719,67.508 h2
  text "Round" at 215.245,67.508 h2
  text "Top Layer - Bottom Layer" at 226.285,67.508 h2
  text "Pad" at 247.399,67.508 h2
  text "Rounded" at 256.359,67.508 h2
  text "c0hn150m155" at 267.824,67.508 h2
  text "-" at 343.258,67.508 h2
  text "-" at 360.457,67.508 h2
  text "1" at 179.686,63.504 h2
  text "3.400mm (133.86mil)" at 189.603,63.504 h2
  text "NPTH" at 207.719,63.504 h2
  text "Square" at 215.245,63.504 h2
  text "Top Layer - Bottom Layer" at 226.285,63.504 h2
  text "Pad" at 247.399,63.504 h2
  text "Rounded" at 256.359,63.504 h2
  text "c0hn340m345" at 267.824,63.504 h2
  text "-" at 343.258,63.504 h2
  text "-" at 360.457,63.504 h2
  text "2" at 179.686,59.5 h2
  text "0.800mm (31.50mil)" at 189.603,59.5 h2
  text "NPTH" at 207.719,59.5 h2
  text "Round" at 215.245,59.5 h2
  text "Top Layer - Bottom Layer" at 226.285,59.5 h2
  text "Pad" at 247.399,59.5 h2
  text "Rounded" at 256.359,59.5 h2
  text "c50hn80" at 267.824,59.5 h2
  text "-" at 343.258,59.5 h2
  text "-" at 360.457,59.5 h2
  text "2" at 179.686,55.496 h2
  text "1.100mm (43.31mil)" at 189.603,55.496 h2
  text "PTH" at 207.719,55.496 h2
  text "Round" at 215.245,55.496 h2
  text "Top Layer - Bottom Layer" at 226.285,55.496 h2
  text "Pad" at 247.399,55.496 h2
  text "Rounded" at 256.359,55.496 h2
  text "c180h110m185" at 267.824,55.496 h2
  text "-" at 343.258,55.496 h2
  text "-" at 360.457,55.496 h2
  text "2" at 179.686,51.491 h2
  text "3.500mm (137.79mil)" at 189.603,51.491 h2
  text "NPTH" at 207.719,51.491 h2
  text "Round" at 215.245,51.491 h2
  text "Top Layer - Bottom Layer" at 226.285,51.491 h2
  text "Pad" at 247.399,51.491 h2
  text "Rounded" at 256.359,51.491 h2
  text "c320hn350m0mx0" at 267.824,51.491 h2
  text "-" at 343.258,51.491 h2
  text "-" at 360.457,51.491 h2
  text "3" at 179.686,47.487 h2
  text "1.100mm (43.31mil)" at 189.603,47.487 h2
  text "NPTH" at 207.719,47.487 h2
  text "Round" at 215.245,47.487 h2
  text "Top Layer - Bottom Layer" at 226.285,47.487 h2
  text "Pad" at 247.399,47.487 h2
  text "Rounded" at 256.359,47.487 h2
  text "c0hn110m115" at 267.824,47.487 h2
  text "-" at 343.258,47.487 h2
  text "-" at 360.457,47.487 h2
  text "4" at 179.686,43.483 h2
  text "1.650mm (64.96mil)" at 189.603,43.483 h2
  text "PTH" at 207.719,43.483 h2
  text "Round" at 215.245,43.483 h2
  text "Top Layer - Bottom Layer" at 226.285,43.483 h2
  text "Pad" at 247.399,43.483 h2
  text "Rectangle" at 256.359,43.483 h2
  text "s250h165m255" at 267.824,43.483 h2
  text "-" at 343.258,43.483 h2
  text "-" at 360.457,43.483 h2
  text "4" at 179.686,39.479 h2
  text "1.730mm (68.11mil)" at 189.603,39.479 h2
  text "NPTH" at 207.719,39.479 h2
  text "Round" at 215.245,39.479 h2
  text "Top Layer - Bottom Layer" at 226.285,39.479 h2
  text "Pad" at 247.399,39.479 h2
  text "Rounded" at 256.359,39.479 h2
  text "c0hn173m178" at 267.824,39.479 h2
  text "-" at 343.258,39.479 h2
  text "-" at 360.457,39.479 h2
  text "4" at 179.686,35.475 h2
  text "3.500mm (137.79mil)" at 189.603,35.475 h2
  text "PTH" at 207.719,35.475 h2
  text "Round" at 215.245,35.475 h2
  text "Top Layer - Bottom Layer" at 226.285,35.475 h2
  text "Pad" at 247.399,35.475 h2
  text "Rounded" at 256.359,35.475 h2
  text "c600h350m605" at 267.824,35.475 h2
  text "-" at 343.258,35.475 h2
  text "-" at 360.457,35.475 h2
  text "8" at 179.686,31.47 h2
  text "0.600mm (23.62mil)" at 189.603,31.47 h2
  text "PTH" at 207.719,31.47 h2
  text "Slot" at 215.245,31.47 h2
  text "Top Layer - Bottom Layer" at 226.285,31.47 h2
  text "Pad" at 247.399,31.47 h2
  text "Rounded" at 256.359,31.47 h2
  text "r210_140h60_130r100m215_145" at 267.824,31.47 h2
  text "1.300mm (51.18mil)" at 343.258,31.47 h2
  text "0.700mm (27.56mil)" at 360.457,31.47 h2
  text "8" at 179.686,27.466 h2
  text "0.900mm (35.43mil)" at 189.603,27.466 h2
  text "NPTH" at 207.719,27.466 h2
  text "Slot" at 215.245,27.466 h2
  text "Top Layer - Bottom Layer" at 226.285,27.466 h2
  text "Pad" at 247.399,27.466 h2
  text "Rounded" at 256.359,27.466 h2
  text "c0hn90_250m260_100" at 267.824,27.466 h2
  text "2.500mm (98.43mil)" at 343.258,27.466 h2
  text "1.600mm (62.99mil)" at 360.457,27.466 h2
  text "14" at 179.686,23.462 h2
  text "0.400mm (15.75mil)" at 189.603,23.462 h2
  text "PTH" at 207.719,23.462 h2
  text "Round" at 215.245,23.462 h2
  text "Top Layer - Bottom Layer" at 226.285,23.462 h2
  text "Via" at 247.399,23.462 h2
  text "Rounded" at 256.359,23.462 h2
  text "(Mixed)" at 267.824,23.462 h2
  text "-" at 343.258,23.462 h2
  text "-" at 360.457,23.462 h2
  text "20" at 179.686,19.458 h2
  text "0.900mm (35.43mil)" at 189.603,19.458 h2
  text "PTH" at 207.719,19.458 h2
  text "Round" at 215.245,19.458 h2
  text "Top Layer - Bottom Layer" at 226.285,19.458 h2
  text "Pad" at 247.399,19.458 h2
  text "(Mixed)" at 256.359,19.458 h2
  text "(Mixed)" at 267.824,19.458 h2
  text "-" at 343.258,19.458 h2
  text "-" at 360.457,19.458 h2
  text "20" at 179.686,15.453 h2
  text "1.000mm (39.37mil)" at 189.603,15.453 h2
  text "PTH" at 207.719,15.453 h2
  text "Round" at 215.245,15.453 h2
  text "Top Layer - Bottom Layer" at 226.285,15.453 h2
  text "Pad" at 247.399,15.453 h2
  text "(Mixed)" at 256.359,15.453 h2
  text "(Mixed)" at 267.824,15.453 h2
  text "-" at 343.258,15.453 h2
  text "-" at 360.457,15.453 h2
  text "1302" at 179.686,11.449 h2
  text "0.300mm (11.81mil)" at 189.603,11.449 h2
  text "PTH" at 207.719,11.449 h2
  text "Round" at 215.245,11.449 h2
  text "Top Layer - Bottom Layer" at 226.285,11.449 h2
  text "Via" at 247.399,11.449 h2
  text "Rounded" at 256.359,11.449 h2
  text "(Mixed)" at 267.824,11.449 h2
  text "-" at 343.258,11.449 h2
  text "-" at 360.457,11.449 h2
  text "1395 Total" at 179.686,7.445 h2
  text "Slot definitions :" at 171.095,4.642 h2
  text "Routed Path Length" at 183.913,4.642 h2
  text "= Calculated from tool start centre position to tool end centre position." at 199.395,4.642 h2
  text "Hole Length" at 183.913,3.04 h2
  text "= Routed Path Length + Tool Size = Slot length as defined in the PCB layout" at 193.691,3.04 h2
  text "NOTES:UNLESS OTHERWISE SPECIFIED" at 169.537,-17.736 h5
  text "1.      THIS BOARD WILL CONFORM TO:" at 169.537,-29.166 h5
  text "IPC-A-600G . CURRENT REV . CLASS Ⅱ" at 181.221,-35.77 h5
  text "IPC-6012B . CURRENT REV . CLASS  Ⅱ" at 181.221,-41.612 h5
  text "2.      ALL UNSPECIFIED DIMENSIONS AND TOLERANCES ARE IN MILLIMETER." at 169.537,-52.534 h5
  text "3.      UNLESS OTHERWISE SPECIFIED ALL HOLE DIMENSIONS APPLY AFTER PLATING." at 169.664,-62.508 h5
  text "4.      MATERIAL FR4 RATING 94V-0 MINIMUM EPOXY GLASS LAMINATE." at 170.299,-74.632 h5
  text "SEE LAYER STACK-UP SEQUENCE FOR OVERALL THICKNESS." at 171.315,-80.728 h5
  text "5.      IMPEDANCE CONTROL (IF APPLICABLE) AND VENDER TO PROVIDE IMPEDANCE PATTERN COUPON AND TEST REPORT." at 170.045,-92.412 h5
  text "SEE IMPEDANCE CONTROL TABLE FOR DETAIL INFORMATION" at 181.221,-100.286 h5
  text "6.      BOARD SHALL BE LPI SOLDER MASKED OVER BARE BOTH SIDES PER" at 168.775,-111.97 h5
  text "COLOR BLUE." at 181.221,-120.352 h5
  text "7.      ALL VIA HOLES SHALL BE COMPLETELY TENTED AND PLUGED." at 168.267,-129.242 h5
  text "8.      SILKSCREEN SHALL BE PERMANENT NON-CONDUCTIVE INK AND WITH NO OVERLAP ON ANY COMPONENT PAD OR THROUGH HOLE." at 168.775,-139.91 h5
  text "COLOR WHITE." at 181.221,-147.53 h5
  text "9.      SURFACE WILL BE FINISHED WITH 1-3 MICRO INCHES IMMERSION GOLD OVER      100 MICRO INCHES NICKEL." at 169.029,-156.928 h5
  text "10.     REMOVE ALL SHAPE EDGES AND BURRS 0.15 MAXIMUM." at 168.775,-164.294 h5
  text "11.     PLEASE USE THE SUPPLIED IPC 356 NETLIST TO VERIFY BOARD BEFORE FABRICATING BOARD." at 168.775,-172.676 h5

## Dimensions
2.5,54 to 112.5,73 on M3-Top Dimensions
2.5,4 to 112.5,7.5 on M3-Top Dimensions
-1.5,1.5 to 127.5,1.5 on M2-Board Dimensions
